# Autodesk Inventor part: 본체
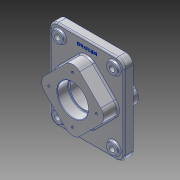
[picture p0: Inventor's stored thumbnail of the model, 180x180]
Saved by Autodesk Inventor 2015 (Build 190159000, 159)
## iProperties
Created: 2026-07
Part Number: 본체
Material: 알루미늄 6061
Document SubType Name: Modeling
Designer: user
Density: 2.7 g/cm^3
Appearance: 알루미늄 - 평지
Mass: 2132.41 g
Surface Area: 955.114 cm^2
Volume: 789.782 cm^3
Author: user
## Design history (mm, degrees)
sketch "스케치1"
  geometry: L1 (-60, 90)-(60, 90); L2 (75, 75)-(75, -75); L3 (60, -90)-(-60, -90); L4 (-75, -75)-(-75, 75); L5 (-75, 90)-(75, -90); L6 (75, 90)-(-75, -90); A1 r 15 centre (60, 75) between (75, 75) and (60, 90); A2 r 15 centre (-60, 75) between (-60, 90) and (-75, 75); A3 r 15 centre (-60, -75) between (-75, -75) and (-60, -90); A4 r 15 centre (60, -75) between (60, -90) and (75, -75); 1 further point
  constraints: 12 end point, 8 point on circle, 8 point on line, 8 tangent, 4 centre point, 3 equal radius, 2 midpoint, 2 parallel, 1 horizontal, 1 perpendicular
  dimensions: "d0" = 150 distance of L5.end L6.end; "d1" = 180 distance of L6.start L5.end; "d2" = 15 radius of A1
extrude "돌출1" new body sketch "스케치1" stored distance "d3" = 18; taper "d4" = 0 deg
sketch "스케치2"
  geometry: L1 (-75, -75)-(-75, 75) reference; L2 (-60, 90)-(60, 90) reference; L3 (75, 75)-(75, -75) reference; L4 (60, -90)-(-60, -90) reference; C1 r 11 at (-55, 70); A1 r 15 centre (-60, -75) between (-75, -75) and (-60, -90) reference; A2 r 15 centre (-60, 75) between (-60, 90) and (-75, 75) reference; A3 r 15 centre (60, 75) between (75, 75) and (60, 90) reference; A4 r 15 centre (60, -75) between (60, -90) and (75, -75) reference; 1 further point
  constraints: 1 centre point
  dimensions: "d5" = 22 diameter of C1; "d6" = 20 distance from line of C1.centre L1; "d7" = 20 distance from line of L2 C1.centre
extrude "돌출2" join sketch "스케치2" distance "d8" = 5; taper "d9" = 0 deg
hole "구멍1" diameter "d12" = 11; stored, may be unused: countersink angle "d16" = 90 deg, drill point angle "d18" = 118 deg; dims "d10" = 10, "d11" = 10, "d13" = 6, "d14" = 4, "d15" = 2, "d17" = 8
sketch "스케치3"
  geometry: L1 (-75, -75)-(-75, 75) reference; L2 (-60, 90)-(60, 90) reference; L3 (75, 75)-(75, -75) reference; L4 (60, -90)-(-60, -90) reference; L5 (-14.142, 56.569)-(-56.569, 14.142); L6 (-56.569, -14.142)-(-14.142, -56.569); L7 (14.142, -56.569)-(56.569, -14.142); L8 (56.569, 14.142)-(14.142, 56.569); C1 r 5.5 at (55, -70) reference; C2 r 5.5 at (55, 70) reference; C3 r 5.5 at (-55, -70) reference; C4 r 11 at (55, -70) reference; C5 r 11 at (55, 70) reference; C6 r 11 at (-55, -70) reference; C7 r 5.5 at (-55, 70) reference; C8 r 11 at (-55, 70) reference; A1 r 15 centre (-60, -75) between (-75, -75) and (-60, -90) reference; A2 r 15 centre (-60, 75) between (-60, 90) and (-75, 75) reference; A3 r 15 centre (60, 75) between (75, 75) and (60, 90) reference; A4 r 15 centre (60, -75) between (60, -90) and (75, -75) reference; A5 r 20 centre (0, 42.426) between (14.142, 56.569) and (-14.142, 56.569); A6 r 20 centre (42.426, 0) between (56.569, -14.142) and (56.569, 14.142); A7 r 20 centre (-42.426, 0) between (-56.569, 14.142) and (-56.569, -14.142); A8 r 20 centre (0, -42.426) between (-14.142, -56.569) and (14.142, -56.569); 5 further points
  constraints: 8 end point, 8 point on circle, 8 point on line, 8 tangent, 4 centre point, 3 equal radius, 3 vertical alignment, 2 horizontal alignment, 2 parallel, 1 perpendicular
  dimensions: "d26" = 100 distance of point (0, 70.711) point (-70.711, 0); "d27" = 20 radius of A5
extrude "돌출3" join sketch "스케치3" distance "d28" = 29; taper "d30" = 0 deg; dims "d29" = 41, "d31" = 0
sketch "스케치4"
  geometry: L1 (-14.142, -56.569)-(-56.569, -14.142) reference; L2 (-56.569, 14.142)-(-14.142, 56.569) reference; L3 (14.142, 56.569)-(56.569, 14.142) reference; L4 (56.569, -14.142)-(14.142, -56.569) reference; C1 r 31 at (0, 0); A1 r 20 centre (-42.426, 0) between (-56.569, 14.142) and (-56.569, -14.142) reference; A2 r 20 centre (0, 42.426) between (14.142, 56.569) and (-14.142, 56.569) reference; A3 r 20 centre (42.426, 0) between (56.569, -14.142) and (56.569, 14.142) reference; A4 r 20 centre (0, -42.426) between (-14.142, -56.569) and (14.142, -56.569) reference; 1 further point
  constraints: 1 centre point, 1 coincident
  dimensions: "d32" = 62 diameter of C1
hole "구멍2" sketch "스케치4" at (0, 0) diameter "d33" = 54; stored, may be unused: countersink angle "d37" = 90 deg, drill point angle "d39" = 118 deg; dims "d34" = 6, "d35" = 62, "d36" = 22, "d38" = 8
hole "구멍3" diameter "d42" = 62; stored, may be unused: countersink angle "d46" = 90 deg, drill point angle "d48" = 0 deg; dims "d43" = 6, "d44" = 62, "d45" = 22, "d47" = 22, "d82" = 10, "d83" = 10
sketch "스케치5"
  geometry: L1 (0, 0)-(0, 48)
  constraints: 2 end point, 1 vertical
  dimensions: "d49" = 48 distance of L1.start L1.end
hole "구멍4" sketch "스케치5" at (0, 48) diameter "d50" = 4.917; stored, may be unused: countersink angle "d54" = 90 deg, drill point angle "d56" = 118 deg; dims "d51" = 10, "d52" = 62, "d53" = 22, "d55" = 13
sketch "스케치6"
  geometry: L1 (-14.142, -56.569)-(-56.569, -14.142) reference; L2 (-56.569, 14.142)-(-14.142, 56.569) reference; L3 (14.142, 56.569)-(56.569, 14.142) reference; L4 (56.569, -14.142)-(14.142, -56.569) reference; L5 (-75, -75)-(-75, 75) reference; L6 (-60, 90)-(60, 90) reference; L7 (75, 75)-(75, -75) reference; L8 (60, -90)-(-60, -90) reference; C1 r 27 at (0, 0) reference; C2 r 5.5 at (55, -70) reference; C3 r 5.5 at (55, 70) reference; C4 r 5.5 at (-55, -70) reference; C5 r 11 at (55, -70) reference; C6 r 11 at (55, 70) reference; C7 r 11 at (-55, -70) reference; C8 r 5.5 at (-55, 70) reference; C9 r 11 at (-55, 70) reference; A1 r 20 centre (-42.426, 0) between (-56.569, 14.142) and (-56.569, -14.142) reference; A2 r 20 centre (0, 42.426) between (14.142, 56.569) and (-14.142, 56.569) reference; A3 r 20 centre (42.426, 0) between (56.569, -14.142) and (56.569, 14.142) reference; A4 r 20 centre (0, -42.426) between (-14.142, -56.569) and (14.142, -56.569) reference; A5 r 15 centre (-60, -75) between (-75, -75) and (-60, -90) reference; A6 r 15 centre (-60, 75) between (-60, 90) and (-75, 75) reference; A7 r 15 centre (60, 75) between (75, 75) and (60, 90) reference; A8 r 15 centre (60, -75) between (60, -90) and (75, -75) reference; 2 further points
  constraints: 1 vertical alignment, 1 other
  dimensions: "d60" = 15 distance from line of L6 point (0, 75)
feature "엠보싱1" sketch "스케치6" dims "d0" = 150, "d1" = 180, "d2" = 15, "d8" = 5, "d61" = 0.5, "d62" = 0
chamfer "모따기1" distance "d64" = 1; stored, may be unused: second distance "d65" = 2, angle "d66" = 45 deg
fillet "모깎기2" dims "d67" = 3
fillet "모깎기3" dims "d68" = 3
fillet "모깎기4" dims "d69" = 3
sketch "스케치7"
  geometry: L1 (0, 0)-(0, -48)
  constraints: 2 end point, 1 vertical
  dimensions: "d70" = 48 distance of L1.start L1.end
hole "구멍5" sketch "스케치7" at (0, -48) diameter "d71" = 4.917; stored, may be unused: countersink angle "d75" = 90 deg, drill point angle "d77" = 118 deg; dims "d72" = 10, "d73" = 62, "d74" = 22, "d76" = 13
fillet "모깎기5" dims "d81" = 3
sketch "스케치8"
  geometry: 1 further point
fillet "모깎기6" dims "d84" = 1
node "솔리드1"
pattern_linear "직사각형 패턴1"
pattern_circular "원형 패턴1" dims angle "d58" = 360 deg
pattern_circular "원형 패턴2" dims angle "d79" = 360 deg
node "절단 모서리 투영1"
node "절단 모서리 투영2"
node "절단 모서리 투영3"
node "절단 모서리 투영4"
